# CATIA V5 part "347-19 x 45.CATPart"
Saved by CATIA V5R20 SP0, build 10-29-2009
Part number: 347-19 x 45
Definition: NONE
Nomenclature: 347-19 x 45
Source: Unknown
Description: 347-19 x 45
Bounding box of the stored display mesh (mm): x 0 to 45, y -15 to 15, z -15 to 15
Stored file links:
  C:\Users\Utente\Desktop\IO LAVORO\3D X SITO CF\X SITO\3D files 347\347-19 x 45.CATPart
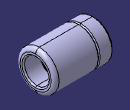
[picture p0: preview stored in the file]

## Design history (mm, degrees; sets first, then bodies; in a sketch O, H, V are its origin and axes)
Body1 "347-19 x 45" (main body)
  Solid1: solid without history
